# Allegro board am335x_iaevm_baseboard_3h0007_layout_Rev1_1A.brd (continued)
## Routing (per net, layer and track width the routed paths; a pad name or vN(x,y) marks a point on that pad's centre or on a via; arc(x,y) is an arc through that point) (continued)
VMMC: length 290.5
  TOP w0.508: v1(121.7,18.45) 120.69,18.45 112.94,26.2 106.46,26.2 104.94,24.68 104.94,23.85 104.05,22.96 99.16,22.96 97.19,20.99 v1(93.89,20.99) ; v1(125.89,53.5) 129.39,53.5 131.8,55.92 151.24,55.92 152.21,54.95 157.95,54.95 v1(158.91,55.92) ; R477.1 81.69,27.85 v1(80.68,27.85) ; v1(157.39,134.21) 157.33,134.28 130.97,134.28 130.78,134.47 v1(128.5,134.47) v1(123.48,134.47) ; v1(121.45,98.14) 120.37,97.07 v1(115.42,97.07)
  BOTTOM w0.508: v1(125.89,53.5) 125.64,53.5 124.88,52.74 124.88,33.12 J19.13 124.94,30.77 124.94,26.07 124.56,25.69 123.1,25.69 121.96,24.55 121.96,18.71 v1(121.7,18.45) ; v1(157.39,134.21) 157.39,98.34 159.03,96.69 159.03,56.95 158.91,56.83 v1(158.91,55.92) ; FB4.2 128.5,134.46 v1(128.5,134.47) ; v1(121.45,98.14) 119.65,99.95 119.65,114.31 121.39,116.05 121.39,118.91 120.56,119.73 120.56,129.2 123.48,132.12 v1(123.48,134.47) ; v1(80.68,27.85) 80.3,27.85 79.67,27.22 79.67,25.18 80.56,24.29 84.75,24.29 85.13,23.91 92.62,23.91 93.89,22.64 v1(93.89,20.99)
  BOTTOM w0.635: FB5.2 v1(115.42,97.07)
VPLL: length 129.3
  TOP w0.508: J19.15 122.66,27.98 v1(108.75,27.98) ; v1(55.84,54.39) 63.99,54.39 65.47,52.92 71.05,52.92 71.67,52.3 72.23,52.3 72.64,51.89 72.89,51.64 73.67,50.87 81.86,50.87 82.46,50.27 86.84,50.27 87.35,50.77 98.33,50.77 98.72,51.15 106.17,51.15 106.68,51.66 109.45,51.66 v1(109.51,51.73) ; R473.2 v1(109.51,37.88)
  BOTTOM w0.121: v1(109.51,51.73) 109.51,51.47
  BOTTOM w0.508: 109.51,51.47 v1(109.51,37.88) 109.51,35.66 108.75,34.9 v1(108.75,27.98) ; v1(55.84,54.39) 55.84,58.96 56.04,59.16 56.04,76.68 FB9.2
VPMIC_VRTC: length 6.4
  TOP w0.203: U4.29 90.05,37.9 90.26,38.11 90.64,38.11 90.74,38.21
  TOP w0.381: 90.74,38.21 v1(91.53,38.21)
  BOTTOM w0.508: v1(91.53,38.21) 91.6,38.29 C97.1 R53.1 93.51,38.39 R60.2
VPP: length 0.6
  TOP w0.381: v2(87.4,81) U2.M5
VPWRIN_FUSED: length 2.7
  TOP w0.502: 74.69,10.2 SW1.1 ; SW1.1 75.6,11.11 ; SW1.1 75.6,9.28
VPWRIN_JCK: length 8.7
  TOP w0.502: 55.79,12.97 J1.1 ; J1.1 53.61,15.15 ; J1.1 57.97,15.15 ; J1.1 55.79,17.33
VREFP_ADC: length 15.6
  TOP w0.102: U2.B9 78.73,84.6 78.33,85 77.1,85
  TOP w0.121: 77.1,85 76.98,84.88 75.62,84.88 74.61,85.89 74.08,85.89 73.52,86.45 72.07,86.45 71.78,86.16 71.78,86.16 71.77,86.15 70.02,86.15 C10.1 C9.1 68.13,86.24 68.01,86.24 67.35,86.91 67.35,89.19
VRTC: length 143.9
  TOP w0.254: U1.8 63.3,100.86 v1(63.28,100.88) 63.28,99.48 63.4,99.36 U1.5
  TOP w0.508: v1(64.05,51.09) 65.65,51.09 66.08,51.52 70.26,51.52 70.37,51.42 70.58,51.42 71.09,50.9 v1(71.28,50.9) ; v1(61.19,59.28) 62.14,58.33 v1(63.66,58.33)
  TOP w0.635: v1(120.05,41.31) 111.29,41.31 107.8,44.8 97.64,44.8 v1(94.14,41.31)
  BOTTOM w0.508: 92.75,40.17 C91.1 v1(94.14,41.31) ; C1.1 63.41,100.75 v1(63.28,100.88) 62.84,100.43 62.84,98.79 62.65,98.6 62.65,96.39 62.05,95.8 62.05,89.43 62.53,88.95 62.53,87.92 63.28,87.17 63.28,83.61 63.91,82.98 63.91,82.09 64.3,81.7 64.3,72.05 61.19,68.93 61.19,61.46 61.24,61.41 61.24,59.82 61.19,59.77 v1(61.19,59.28) ; v1(63.66,58.33) 63.66,56.74 64.31,56.1 64.31,52.81 64.05,52.55 v1(64.05,51.09) 63.47,50.52 61.22,50.52 R505.2 ; v1(71.28,50.9) 75.92,50.9 77.38,49.44 77.38,46.27 77.76,45.88 77.76,41.19 78.43,40.52 78.43,40.39 80.48,38.34 82.32,38.34 v1(83.1,37.57) 83.6,37.06 R54.2
  BOTTOM w0.635: J19.3 121.89,55.54 121.89,46.65 120.05,44.8 v1(120.05,41.31)
  vias: v1(86.14,25.31) v1(86.14,24.55)
VUSB_VBUS0: length 97.4
  TOP w0.508: v1(104.66,100.62) 97.36,100.62 R563.1
  TOP w0.762: v1(137.51,160.57) C262.1 v1(136.33,159.38)
  LY3 w0.508: v1(133.51,152.37) v1(105.47,152.37)
  LY4 w0.508: v1(104.66,100.62) 103.69,101.59 103.69,114.69 104.48,115.48 104.48,119.54 104.02,120 104.02,122.85 104.38,123.21 104.38,146.64 104.02,147 104.02,151.7 104.7,152.37 v1(105.47,152.37)
  BOTTOM w0.502: J36.1 136.44,154.94 ; J36.1 137.48,153.9 ; J36.1 135.39,153.9 ; J36.1 136.44,152.86
  vias: v1(132.02,164.76) v1(132.88,164.76) v1(133.77,164.73) v1(134.15,151.61) v1(134.72,152.37) v1(135.48,151.61) v1(136.05,152.37)
VUSB_VBUS1: length 114.8
  TOP w0.502: 150.95,157.71 J37.1 ; J37.1 151.99,156.67 ; J37.1 151.99,158.75 ; J18.1 149.45,166 ; J18.1 150.44,165.01 ; J18.1 149.45,164.02 ; J18.1 148.46,165.01
  TOP w0.508: v1(104.76,106.31) 103.92,105.47 93.7,105.47 93.38,105.15 R564.1
  TOP w0.635: v1(144.06,160.44) C265.1 v1(145.16,159.19)
  LY3 w0.508: v1(105.17,150.13) 105.17,150.18 106.73,151.74 130.25,151.74 131.46,150.53 140.88,150.53 v1(141.77,151.42)
  LY4 w0.508: v1(105.17,150.13) 105.17,148.68 105.7,148.14 105.7,109.31 104.76,108.37 v1(104.76,106.31)
  BOTTOM w0.502: 150.95,157.71 J37.1 ; J37.1 151.99,158.75 ; J37.1 153.03,157.71 ; J37.1 151.99,156.67 ; 149.45,164.02 J18.1 ; J18.1 150.44,165.01 ; J18.1 148.46,165.01 ; J18.1 149.45,166
  vias: v1(142.4,152.37) v1(143.1,151.42) v1(143.67,152.37) v1(144.37,151.42) v1(147.55,163.8) v1(148.31,163.87) v1(149.14,163.74)
N17759: length 6.1
  TOP w0.121: Y2.1 104.45,83.75 104.18,83.48 C5.1 100.95,83.48 R8.2 R7.1
N120395: length 1.7
  TOP w0.121: R50.1 84.09,18.18 D3.2
N124510: length 2.9
  TOP w0.121: v1(31.41,95.54) J2.4
  BOTTOM w0.121: R73.2 v1(31.41,95.54)
N150689: length 13.1
  TOP w0.121: R5.2 68.25,79.41 67.79,78.96 67.79,78.59 67.8,78.58 67.8,76.44 67.47,76.11 66.8,76.11 C3.2 62.86,76.02 61.76,77.13 61.76,78.78 Y1.1
N194366: length 15
  TOP w0.102: U2.A9 77.1,84.6
  TOP w0.121: 67.35,83.48 67.35,85.76 67.7,85.41 67.96,85.41 C9.2 C10.2 70.14,85.25 70.14,85.51 70.54,85.9 71.87,85.9 71.88,85.91 71.89,85.91 72.18,86.2 73.38,86.2 73.95,85.64 74.51,85.64 75.52,84.63 77.07,84.63 77.1,84.6
N17034041: length 2.7
  TOP w0.121: v1(153.96,69.13) SW3.1
  BOTTOM w0.121: R114.2 v1(153.96,69.13)
N17034069: length 2.7
  TOP w0.121: v1(153.96,66.59) SW3.2
  BOTTOM w0.121: R115.2 v1(153.96,66.59)
N17034107: length 2.7
  TOP w0.121: v1(153.96,64.05) SW3.3
  BOTTOM w0.121: R116.2 v1(153.96,64.05)
N17034117: length 2.7
  TOP w0.121: v1(153.96,61.51) SW3.4
  BOTTOM w0.121: R117.2 v1(153.96,61.51)
N17034161: length 2.7
  TOP w0.121: v1(153.96,58.97) SW3.5
  BOTTOM w0.121: R118.2 v1(153.96,58.97)
N17034171: length 2.7
  TOP w0.121: v1(153.96,56.43) SW3.6
  BOTTOM w0.121: R119.2 v1(153.96,56.43)
N17034215: length 2.7
  TOP w0.121: v1(153.96,53.89) SW3.7
  BOTTOM w0.121: R120.2 v1(153.96,53.89)
N17034225: length 2.7
  TOP w0.121: SW3.8 v1(153.96,51.35)
  BOTTOM w0.121: R121.2 v1(153.96,51.35)
N17107785: length 3.6
  TOP w0.203: U4.18 93.1,33.49 94.04,34.43 v1(94.04,35.01)
  BOTTOM w0.381: C98.1 94.4,34.66 v1(94.04,35.01)
N17298950: length 2.2
  TOP w0.121: U18.6 C179.1
N17298952: length 5
  TOP w0.121: C177.1 107.78,24.37 108.55,24.37 108.72,24.19 108.72,22.01 108.47,21.75 U18.2
N17298960: length 2.5
  TOP w0.121: U18.3 105.83,20.48 C176.2
N17298962: length 2.2
  TOP w0.121: 104.94,19.09 105.07,19.21 U18.4
N17298964: length 2.2
  TOP w0.121: U18.5 105.07,17.94 C178.2
N17298974: length 2.4
  TOP w0.121: U18.1 105.57,23.02 C176.1
N17345501: length 2.7
  TOP w0.121: v1(153.96,91.73) SW4.1
  BOTTOM w0.121: R122.2 v1(153.96,91.73)
N17345515: length 2.7
  TOP w0.121: v1(153.96,89.19) SW4.2
  BOTTOM w0.121: R123.2 v1(153.96,89.19)
N17345519: length 2.7
  TOP w0.121: v1(153.96,86.65) SW4.3
  BOTTOM w0.121: R124.2 v1(153.96,86.65)
N17345529: length 2.7
  TOP w0.121: v1(153.96,84.11) SW4.4
  BOTTOM w0.121: R125.2 v1(153.96,84.11)
N17345551: length 2.7
  TOP w0.121: v1(153.96,81.57) 155.61,81.57
  BOTTOM w0.121: R126.2 v1(153.96,81.57)
N17345553: length 2.7
  TOP w0.121: v1(153.96,79.03) SW4.6
  BOTTOM w0.121: R127.2 v1(153.96,79.03)
N17345567: length 2.7
  TOP w0.121: v1(153.96,76.49) SW4.7
  BOTTOM w0.121: R128.2 v1(153.96,76.49)
N17345577: length 2.7
  TOP w0.121: v1(153.96,73.95) SW4.8
  BOTTOM w0.121: R129.2 v1(153.96,73.95)
N17563948: length 121.5
  TOP w0.121: v1(40.5,116.32) 29.53,116.32 28.05,114.85 25.8,114.85 25.68,114.97 24.4,114.97 22.87,116.5 v1(22.86,116.5) ; Q1.G 10.44,88.54 R86.2 10.45,89.45 10.2,89.7 9.82,89.7 v1(9.31,90.21) ; 72.68,112.18 v1(73.62,112.18) ; R84.1 76.72,104.66 v1(76.72,104.94) ; R509.1 v1(89.95,112.51)
  LY3 w0.133: v1(73.62,112.18) 73.67,112.13 v1(76.49,112.13) 76.52,112.13 77.38,112.99 89.47,112.99 v1(89.95,112.51) ; v1(73.62,116.5) 73.42,116.7 41.49,116.7 41.11,116.32 v1(40.5,116.32)
  BOTTOM w0.121: v1(22.86,116.5) 22.86,115.39 22.14,114.67 22.14,112.08 21.2,111.15 21.2,104.38 16.55,99.73 12.61,99.73 9.57,96.7 9.57,92.62 9.31,92.35 v1(9.31,90.21) ; v1(73.62,116.5) v1(73.62,112.18) ; v1(76.49,112.13) 76.72,111.9 v1(76.72,104.94)
N17563994: length 1.9
  TOP w0.121: D4.2 5.48,88.43 v1(4.51,88.43)
  BOTTOM w0.121: R80.1 v1(4.51,88.43)
N17563997: length 2.7
  TOP w0.121: D4.1 7.66,86.16 Q1.D
N17564510: length 2.8
  TOP w0.121: D5.1 5.75,82.09 Q2.D
N17564514: length 2
  TOP w0.121: D5.2 v1(4.48,84.09)
  BOTTOM w0.121: R81.1 4.58,84.11 4.57,84.09 v1(4.48,84.09)
N17564644: length 2.8
  TOP w0.121: D6.1 5.75,77.65 Q3.D
N17564648: length 2
  TOP w0.121: v1(4.48,79.67) 5.48,79.67 D6.2
  BOTTOM w0.121: R82.1 v1(4.48,79.67)
N17564780: length 2.7
  TOP w0.121: Q4.D 5.62,73.2 D7.1
N17564784: length 2
  TOP w0.121: D7.2 v1(4.48,75.33)
  BOTTOM w0.121: R83.1 4.58,75.35 4.57,75.33 v1(4.48,75.33)
N17564892: length 199.4
  TOP w0.121: v1(9.44,85.13) 10.32,85.13 10.58,84.87 R93.2 10.57,84.1 Q2.G ; R87.1 77.25,101.81 v1(76.69,102.37) 77,102.68 77,104.56 R88.1 v1(78.55,106.11) ; v1(77.79,112.2) 85.08,112.2 R510.1 ; v1(22.64,156.69) v1(53.38,156.69)
  LY3 w0.133: v1(76.69,102.37) 76.48,102.59 73.26,102.59 72.93,102.91 68.28,102.91 67.8,103.39 53.28,103.39 52.36,104.3 43.19,104.3 40.97,102.08 23.72,102.08 23.46,101.82 23.09,101.82 22.18,102.73 v1(22.18,103.38)
  LY4 w0.133: v1(77.79,112.2) 78.55,111.44 v1(78.55,106.11)
  BOTTOM w0.121: v1(53.38,156.69) 58.14,156.69 v1(58.58,156.25) ; v1(22.64,156.69) 22.64,148.2 23.21,147.63 23.21,117.41 23.36,117.26 23.36,114.97 23.21,114.82 23.21,112.34 21.45,110.57 21.45,104.73 22.18,104 v1(22.18,103.38) 22.15,103.38 18.24,99.47 12.73,99.47 9.82,96.56 9.82,87.17 9.44,86.78 v1(9.44,85.13)
N17564904: length 244.4
  TOP w0.121: v1(24.04,156.12) v1(54.14,156.12) ; R89.1 R90.1 70.52,103.42 59.47,103.42 58.46,104.42 42.76,104.42 41.28,102.94 35.65,102.94 35.63,102.97 35.26,102.97 35.24,102.94 v1(23.66,102.94) ; Q3.G 9.12,79.67 R95.2 10.58,80.3 v1(10.07,80.81) ; R511.1 v1(87.79,112.51)
  LY3 w0.133: v1(87.79,112.51) 79.21,112.51 77.37,110.67 71,110.67 70.87,110.81 48.63,110.81 42.61,104.79 34.23,104.79 32.38,102.94 v1(23.66,102.94)
  BOTTOM w0.121: v1(10.07,80.81) 10.07,96.43 12.86,99.22 18.91,99.22 22.63,102.94 v1(23.66,102.94) 23.66,104.05 21.69,106.02 21.69,110.46 23.46,112.23 23.46,114.64 23.61,114.79 23.61,120 23.46,120.15 23.46,148.24 23.13,148.58 23.13,155.21 v1(24.04,156.12) ; v1(57.31,156.12) v1(54.14,156.12)
N17564916: length 152.7
  TOP w0.121: v1(46.52,136.56) 48.42,134.66 53.55,134.66 54.44,133.77 58.84,133.77 v1(59.6,133.01) ; v1(10.58,76.08) R94.2 10.57,75.21 Q4.G ; v1(23.28,102.27) 23.51,102.5 34.76,102.5 34.78,102.53 v1(35.44,102.53) 35.9,102.53 35.93,102.5 41.19,102.5 42.86,104.18 58.33,104.18 59.34,103.17 69.68,103.17 71.03,101.81 71.03,99.48 71.28,99.23 71.45,99.23 71.46,99.23 71.87,99.23 71.88,99.23 72.47,99.23 73.51,98.19 73.51,97.64 R91.1 ; v1(36.64,113.07) 39.05,113.07 41.59,115.61 R92.1 v1(46.9,117.28)
  BOTTOM w0.121: v1(46.52,136.56) 46.52,135.29 46.9,134.91 v1(46.9,117.28) ; v1(23.28,102.27) 22.31,102.27 19.01,98.97 13.04,98.97 10.32,96.25 10.32,81.7 10.58,81.44 v1(10.58,76.08) ; R512.1 v1(59.6,133.01) ; v1(36.64,113.07) 35.44,111.87 v1(35.44,102.53)
N17574941: length 2.1
  TOP w0.121: R1.1 59.46,100.86 U1.1
N17684279: length 4.4
  TOP w0.121: R239.1 v1(129.45,79.79)
  BOTTOM w0.102: J8.12 132.12,79.54 130.72,79.54
  BOTTOM w0.121: 130.72,79.54 129.7,79.54 v1(129.45,79.79)
N17684406: length 4.9
  TOP w0.121: U4.33 88.45,37.36 88.36,37.44 v1(88.36,37.53)
  BOTTOM w0.203: v1(88.36,37.53) 88.07,37.53 87.62,37.98 87.62,39.03 87.79,39.2 R63.1
N17710761: length 4.8
  TOP w0.102: v2(84.2,79.4) U2.J3
  BOTTOM w0.102: 84.2,77.4 v2(84.2,79.4)
  BOTTOM w0.121: 84.2,77.4 84.2,76.93 83.36,76.09 83.36,75.93 R22.2
N17828529: length 2.5
  TOP w0.102: U2.G2 83,79 83.35,78.65 v2(83.35,77.63)
  BOTTOM w0.102: 83.12,77.4 v2(83.35,77.63)
  BOTTOM w0.121: TP2.1 83.03,77.32 83.12,77.4
N18136628: length 2.7
  TOP w0.121: v1(139.74,72.05) 139.67,71.98 U7.7
  BOTTOM w0.121: v1(139.74,72.05) 139.74,70.9
N18365790: length 3
  TOP w0.203: U4.39 85.72,35.09 85.71,35.1 85.02,35.1 v1(84.78,35.34)
  BOTTOM w0.381: R57.1 84.65,35.47 v1(84.78,35.34)
N18368859: length 1.9
  TOP w0.203: R69.2 93.26,23.78 U6.7
N19440113: length 0.4
  TOP w0.121: U24.B2 U24.B1
N19440133: length 0.4
  TOP w0.121: U24.D2 U24.D1
N19440219: length 2.9
  TOP w0.121: U24.A3 U24.B3 U24.C4 U24.D4 155.59,144.71 C264.1
N19490589: length 9.9
  TOP w0.102: 77.1,80.08 77.2,80.08 77.21,80.07 77.93,80.07 U2.A3
  TOP w0.121: 77.1,80.08 76.39,80.08 75.74,79.42 71.89,79.42 71.51,79.03 71.16,79.03 70.78,78.66 69.9,78.66 TP24.1
N19558182: length 2.1
  TOP w0.121: R544.1 59.97,35.65 U32.2
N19577113: length 3.4
  TOP w0.121: U4.26 91.25,37.21 91.41,37.38 v1(92.49,37.38)
  BOTTOM w0.121: v1(92.49,37.38) 92.11,36.99 92.11,36.36 91.86,36.11
N19577116: length 4.7
  TOP w0.121: v1(93.38,34.45) 92.82,33.89 U4.19
  BOTTOM w0.121: R60.1 93,36.99 92.64,36.63 92.64,35.2 v1(93.38,34.45)
N21001557: length 9.1
  TOP w0.121: SW5.1 6.8,43.4 7.94,44.54 v1(7.94,45.25) 7.07,45.25 6.8,45.52 SW5.2
  BOTTOM w0.121: R112.2 R156.2 v1(7.94,45.25)
N21001559: length 8
  TOP w0.635: v1(10.83,43.34) 10.8,43.25 SW5.3 ; SW5.4 v1(10.8,45.45)
  BOTTOM w0.121: v1(10.83,43.34) 10.8,43.38 v1(10.8,45.45) 10.83,45.48 R559.1 R560.2
N21339295: length 1.8
  TOP w0.121: R23.2 129.39,161.73 128.6,160.95 Q5.D

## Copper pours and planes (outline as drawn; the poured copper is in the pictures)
DGND on TOP: 155.36,146.34 154.6,146.34 154.09,145.83 154.09,143.8 153.96,143.67 153.07,143.67 152.95,143.8 152.95,144.56 152.44,144.56 151.42,145.58 147.48,145.58 147.36,145.45 147.36,142.91 147.74,142.53 156.37,142.53 156.5,142.66 156.5,146.34 156.37,146.34 156.25,146.21 156.25,145.83 155.99,145.58 155.99,144.06 155.1,144.06 155.1,145.83 155.36,146.09
DGND on LY2_GND, LY5_GND: 1.27,1.27 168.73,1.27 168.73,168.73 1.27,168.73
V1_8D on LY4: 134.78,125.64 137.96,125.64 137.96,116.62 134.28,116.62 134.28,50.08 132.24,50.08 132.24,88.3 129.83,88.3 129.83,122.34 134.53,122.34 134.53,125.39
V3_3D on TOP: 113.96,24.93 112.05,24.93 111.92,24.8 111.92,23.91 111.67,23.66 110.65,23.66 110.65,22.64 110.78,22.52 113.83,22.52 113.96,22.64
V3_3D on BOTTOM: 111.42,22.01 113.58,22.01 113.96,22.39 113.96,24.68 113.7,24.93 111.29,24.93 111.16,24.8 111.16,22.26
V3_3D on LY4: 47.28,139.1 47.28,139.23 36.87,139.23 36.87,115.1 10.07,115.1 10.07,95.16 28.36,95.16 28.36,61.25 23.66,61.25 23.66,51.35 12.1,51.35 12.1,47.79 1.43,47.79 1.43,1.31 131.48,1.31 131.48,25.82 102.27,25.82 102.27,7.66 51.22,7.66 51.22,72.33 32.93,72.33 32.93,99.35 13.63,99.35 13.63,104.3 68.24,104.3 68.24,120.31 75.6,120.31 75.6,146.85 64.43,146.85 64.43,139.1
V5_0D on TOP: 155.1,147.87 155.36,147.61 155.36,146.98 153.33,146.98 152.82,146.47 152.82,144.94 152.69,144.82 152.44,144.82 151.42,145.83 147.36,145.83 146.85,146.34 146.85,147.99 147.48,148.63 152.06,148.63 152.82,147.87
V5_0D on LY4: 152.95,148.63 152.95,70.14 134.66,70.14 134.66,116.37 138.21,116.37 138.21,125.89 134.53,125.89 134.15,125.51 134.15,122.97 129.83,122.97 129.83,148.63
VBAT on TOP: 83.35,10.58 93.38,10.58 93.89,11.09 93.89,14.01 91.48,16.42 91.48,18.71 91.22,18.96 91.22,21.88 87.79,21.88 87.54,21.63 86.65,21.63 86.65,21.75 86.52,21.75 86.52,22.26 82.97,22.26 82.97,18.96 86.14,18.96 86.27,18.83 86.27,14.9 85.89,14.52 78.4,14.52 78.33,14.45 77.82,14.45 77,13.63 77,8.8 77.25,8.55 78.9,8.55 79.67,9.31 79.67,11.21 80.05,11.59 82.33,11.59
VBAT on TOP: 10.96,99.86 14.77,99.86 14.9,99.99 14.9,100.62 14.64,100.88 10.96,100.88
VBAT on TOP: 159.8,146.47 159.8,149.39 159.55,149.64 158.15,149.64 157.39,148.88 157.39,148.25 156.63,147.48 156.63,146.85 157.14,146.85 157.52,146.47
VBAT on LY4: 106.21,163.74 106.21,157.9 120.43,157.9 120.43,42.46 98.34,42.46 98.34,37.88 83.86,37.88 83.86,22.9 56.68,22.9 56.68,84.11 50.71,84.11 50.71,103.8 14.01,103.8 14.01,99.61 33.44,99.61 33.44,72.63 51.6,72.63 51.6,8.04 101.89,8.04 101.89,26.33 131.86,26.33 131.86,87.29 128.82,87.29 128.82,148.88 153.33,148.88 153.33,147.99 159.3,147.99 159.3,154.47 134.53,154.47 134.53,163.74
VBUS1_OTG_CAP on TOP: 153.38,161.15 153.38,156.91 154.09,156.2 159.6,156.2 159.9,156.5 159.9,160.13 158.66,161.38 153.61,161.38
VDD1_SMPS on TOP: 72.3,37.68 74.99,37.68 75.25,37.43 75.25,36.21 75.02,35.98 72.45,35.98 72.27,36.16 72.27,37.65
VDD1_SMPS on TOP: 80.43,43.34 81.7,43.34 82.21,43.85 82.21,46.33 80.05,46.33 80.05,43.73
VDD1_SMPS on LY3: 125.2,51.22 125.2,45.5 121.7,45.5 121.7,44.11 76.11,44.11 76.11,34.07 66.71,34.07 66.71,47.28 117.39,47.28 117.39,51.22
VDD2_SMPS on TOP: 76.24,36.49 77.76,36.49 78.27,36.99 78.27,38.65 78.14,38.77 76.24,38.77 76.11,38.65 76.11,36.61
VDD2_SMPS on TOP: 68.74,49.06 69.51,49.06 69.89,48.68 70.52,48.68 70.78,48.42 70.78,47.28 70.27,46.77 69.89,46.77 69.76,46.9 69.76,47.79 69.63,47.92 68.74,47.92
VDD2_SMPS on LY4: 78.14,39.03 75.98,39.03 75.98,32.63 72.43,32.63 72.43,48.93 69.25,48.93 69.25,29.48 78.14,29.48
VDD3_SMPS on TOP: 90.97,44.74 93.13,44.74 93.26,44.87 93.26,46.52 92.87,46.9 91.1,46.9 90.84,46.65 90.84,44.87
VDD3_SMPS on BOTTOM: 92.62,49.69 92.62,45 92.24,44.61 90.33,44.61 89.95,45 89.95,49.69 89.98,49.73 89.98,49.69
VDD_CORE on TOP: 72.55,46.77 72.55,45.76 72.81,45.5 75.09,45.5 75.6,46.01 75.6,46.9 75.22,47.28 73.06,47.28
VDD_CORE on BOTTOM: 73.06,47.28 72.55,46.77 72.55,45.76 72.81,45.5 75.09,45.5 75.6,46.01 75.6,46.77 75.09,47.28
VDD_CORE on LY3: 85.38,83.86 86.91,83.86 87.03,83.73 87.03,75.86 86.02,74.84 77.63,74.84 77.63,70.01 77.38,69.76 64.55,69.76 64.17,70.14 64.17,77.89 64.81,78.52 75.22,78.52 77.38,80.68 82.21,80.68
VDD_CORE on LY4: 82.33,86.97 82.33,81.57 86.02,81.57 86.02,82.33 86.78,82.33 86.78,83.98 88.56,83.98 88.56,88.49 88.37,88.68 85.32,88.68 84.43,87.79 83.92,87.79 83.1,86.97
VDD_MPU on TOP: 72.25,34.96 74.56,34.96 74.92,34.61 74.92,32.98 74.61,32.68 73.87,32.68 73.29,33.26 72.3,33.26 72.17,33.39 72.17,34.89
VDD_MPU on LY3: 84.37,88.43 84.62,88.18 84.62,87.79 84.24,87.41 84.24,85.25 83.73,84.75 82.33,84.75 81.83,84.24 81.83,83.86 81.19,83.22 80.3,83.22 80.17,83.1 78.14,83.1 75.86,80.81 67.22,80.81 66.97,80.56 64.55,80.56 64.43,80.68 64.43,82.71 73.06,82.71 74.21,83.86 76.11,83.86 79.03,86.78 79.54,86.78 79.92,86.4 80.43,86.4 80.94,85.89 81.44,86.4 81.44,88.43
VDDS_DDR on LY3: 67.09,69.51 67.09,54.52 67.35,54.27 103.67,54.27 105.19,55.79 105.19,65.7 106.46,66.97 106.46,69.68 106.01,70.14 104,70.14 103.36,69.51 91.5,69.51 90.49,68.49 90.49,66.41 89.57,65.49 89.06,65.49 89.06,66.66 87.79,67.93 87.79,69.51 85.05,69.51 86.93,67.63 86.93,65.82 86.91,65.8 86.35,65.8 86.32,65.82 86.32,66.89 83.7,69.51
VDDS_RTC on LY4: 80.43,82.9 80.43,80.62 69.82,80.62 69.82,81.83 71.6,83.6 79.73,83.6
VDDSHV2 on LY3: 19.87,113.04 19.87,110.65 22.59,107.94 42.07,107.94 47.64,113.5 76.44,113.5 76.85,113.91 79.49,113.91 80.71,115.12 80.71,117.94 80.12,118.53 77.15,118.53 76.72,118.1 76.72,116.89 75.98,116.15 73.23,116.15 73.14,116.06 43.93,116.06 43.6,116.39 42.02,116.39 38.11,112.48 23.25,112.48 22.52,113.22 20.05,113.22
VDDSHV4 on LY4: 42.2,143.42 42.2,164.88 61.51,164.88 61.51,163.61 105.96,163.61 105.96,157.64 117,157.64 117,148.75 114.34,148.75 114.34,155.49 76.62,155.49 76.62,147.23 57.7,147.23 57.7,143.42
VDDSHV6 on LY4: 141.26,1.27 141.26,1.43 132.24,1.43 132.24,49.57 134.66,49.57 134.66,69.89 153.45,69.89 153.45,147.61 159.68,147.61 159.68,154.85 134.91,154.85 134.91,163.87 61.76,163.87 61.76,165.26 41.82,165.26 41.82,143.42 58.33,143.42 58.33,146.98 63.92,146.98 63.92,139.74 36.49,139.74 36.49,115.35 9.82,115.35 9.82,94.65 28.1,94.65 28.1,61.51 23.41,61.51 23.41,51.73 11.72,51.73 11.72,48.17 1.31,48.17 1.31,168.69 143.42,168.69 143.42,168.73 168.28,168.73 168.73,168.28 168.73,1.72 168.28,1.27
AM335X_VDDS on LY3: 80.56,81.95 80.56,80.91 82.18,80.91 85.38,84.11 87.29,84.11 87.29,81.63 87.41,81.51 88.62,81.51 88.68,81.57 88.68,83.79 89.38,83.79 89.38,85.13 88.81,85.13 88.56,85.38 88.56,88.43 88.68,88.56 89.57,88.56 89.83,88.3 91.48,88.3 92.49,89.32 94.14,89.32 94.14,90.46 94.02,90.59 91.99,90.59 91.86,90.52 90.84,89.51 85.7,89.51 85.57,89.64 85.57,94.14 85.59,94.16 85.59,95.09 87.39,96.89 87.39,97.4 87.77,97.78 88.23,97.78 88.65,98.2 88.65,98.75 87.92,99.48 84.03,99.48 83.1,98.54 83.1,93 81.95,93 80.68,91.73 80.68,88.94 81.06,88.56 84.37,88.56 84.75,88.18 84.75,87.67 84.37,87.29 84.37,85.13 83.86,84.62 82.46,84.62 81.95,84.11 81.95,83.6 81.83,83.48 81.83,83.35 81.44,82.97 81.44,82.33 81.25,82.14 80.75,82.14
AM335X_VDDS_DDR on BOTTOM: 81.32,80.81 83.73,80.81 83.98,80.56 86.78,80.56 86.91,80.68 86.91,81.19 86.78,81.32 83.98,81.32 83.86,81.44 83.86,81.83 83.6,82.08 81.32,82.08 81.19,81.95 81.19,80.94
AM335X_VDDS_DDR on LY4: 82.33,81.32 82.33,80.56 87.79,80.56 87.79,81.44 88.56,81.44 88.56,81.98 88.81,82.23 89.29,82.23 89.83,81.7 92.62,81.7 92.62,82.87 92.42,83.07 92.01,83.07 91.88,83.2 91.88,83.25 91.27,83.86 86.91,83.86 86.91,82.21 86.14,82.21 86.14,81.32
AM335X_VDDSHV3 on LY3: 89.45,88.43 88.75,88.43 88.62,88.3 88.62,86.52 88.87,86.27 91.73,86.27 92.37,86.91 92.87,86.91 93.51,87.54 94.14,87.54 94.27,87.67 94.27,88.94 94.14,89.06 92.49,89.06 91.48,88.05 89.83,88.05
AM335X_VDDSHV6 on LY3: 48.93,83.98 66.84,83.98 67.86,82.97 72.94,82.97 74.14,84.17 76.05,84.17 79.03,87.16 79.54,87.16 80.05,86.65 80.43,86.65 80.81,86.27 81.06,86.27 81.32,86.52 81.32,88.43 80.94,88.43 80.17,89.19 80.17,91.48 79.49,92.16 76.77,92.16 75.67,91.06 75.67,88.24 73.57,86.14 48.81,86.14 48.81,84.11
AM335X_VDDSHV6 on LY4: 88.81,82.08 89.22,82.08 89.45,81.85 89.45,81.7 89.57,81.57 92.62,81.57 92.62,79.79 93.38,79.79 93.38,79.03 91.1,79.03 91.1,77.76 91.13,77.73 91.1,77.7 91.1,76.81 80.56,76.81 80.56,89.19 83.1,89.19 83.1,87.16 82.21,87.16 82.21,80.3 87.92,80.3 87.92,81.06 88.18,81.32 88.56,81.32 88.68,81.44 88.68,81.95
LDO_VRTC on TOP: 82.59,25.95 83.86,25.95 83.86,23.02 83.73,22.9 82.71,22.9 82.59,22.77 81.83,22.77 81.83,24.29 82.59,25.06
PWR_SMPS3 on TOP: 89.06,38.44 89.06,36.74 89.45,36.74 89.45,38.21 89.88,38.65 89.88,39 89.62,39.25 89.39,39.25 89.22,39.08 89.22,38.59
PWR_SWIO on TOP: 94.91,29.88 96.43,29.88 96.56,30.01 96.56,35.09 95.29,35.09 94.02,33.82 94.02,32.17 93.76,31.91 93.51,31.91 93.51,31.66 94.02,31.66 94.14,31.53 94.14,30.64
PWR_VAUX33 on LY4: 87.03,28.87 87.03,27.98 87.41,27.6 94.14,27.6 94.65,28.1 94.65,28.87 94.27,29.25 90.33,29.25 89.95,28.87
PWR_VDAC on TOP: 97.7,36.74 97.7,35.22 94.02,35.22 93.64,34.84 91.99,34.84 91.99,35.34 93,35.34 94.14,36.49 94.91,36.49 95.16,36.74
PWR_VDD1_SMPS on TOP: 80.17,41.31 81.95,41.31 82.46,41.82 87.41,41.82 88.05,41.19 88.18,41.19 88.56,40.8 89.32,40.8 89.32,45.38 88.81,45.88 83.1,45.88 82.46,45.25 82.46,43.6 81.83,42.96 80.43,42.96 80.05,42.58 80.05,41.44
PWR_VDD2_SMPS on TOP: 84.11,32.8 84.11,33.06 84.49,33.44 85.64,33.44 85.89,33.18 86.4,33.18 86.4,32.93 85.76,32.93 85.64,33.06 85.25,33.06 85,32.8
PWR_VDD2_SMPS on TOP: 76.49,35.98 77.76,35.98 79.03,37.25 80.81,37.25 80.94,37.12 80.94,31.91 80.56,31.53 79.54,31.53 77.89,33.18 76.75,33.18 76.49,33.44
PWR_VDD3_SMPS on TOP: 89.57,36.74 89.57,38.14 90.21,38.77 90.21,38.9 90.52,39.22 91.35,39.22 91.35,44.23 91.48,44.36 93.13,44.36 93.26,44.23 93.26,39.03 93,38.77 90.84,38.77 90.46,38.39 90.21,38.39 89.83,38.01 89.83,36.74
PWR_VDDIO on TOP: 93,30.39 93,30.64 92.62,31.03 91.6,31.03 91.6,30.26 92.24,30.26 92.49,30.01 92.62,30.01
PWR_VDIG2 on TOP: 87.92,27.47 87.92,28.36 88.3,28.74 88.3,29.63 88.68,30.01 88.94,30.01 88.94,27.47
PWR_VIO_SMPS on TOP: 97.57,35.09 97.57,29.88 97.83,29.63 99.48,29.63 99.73,29.37 99.73,27.98 99.86,27.85 102.65,27.85 102.91,28.1 102.91,30.14 100.24,32.8 100.24,34.96 100.11,35.09
PWR_VIO_SMPS on BOTTOM: 93.13,32.8 96.18,32.8 96.56,32.42 100.88,32.42 101.26,32.04 101.26,30.9 100.75,30.39 95.54,30.39 94.02,31.91 93.13,31.91
PWR_VMMC on TOP: 86.02,28.1 86.27,28.1 86.52,28.36 86.52,29.5 87.41,30.39 87.41,30.96 87.48,31.03 87.79,31.03 87.79,29.88 87.67,29.76 87.41,29.76 87.29,29.63 87.29,27.47 87.16,27.34 86.02,27.34
PWR_VPLL on TOP: 93.26,36.87 92.49,36.87 92.24,36.61 92.24,35.85 92.75,35.85 92.75,36.36 93,36.61 93.26,36.61
USB5V_FB on TOP: 155.36,146.85 153.45,146.85 153.07,146.47 153.07,144.06 153.33,143.8 153.83,143.8 153.96,143.93 153.96,145.83 154.6,146.47 155.36,146.47
VBCKUPBAT on TOP: 92.75,38.39 92.24,38.39 91.73,37.88 91.1,37.88 90.72,37.5 90.72,36.61 90.97,36.61 90.97,37.25 91.35,37.63 92.37,37.63 92.75,38.01
VPWRIN_FUSED on TOP: 65.95,8.8 75.73,8.8 76.49,9.56 76.49,13.88 74.59,15.79 74.59,22.39 64.05,22.39 63.54,21.88 63.54,11.21
VPWRIN_JCK on TOP: 51.6,12.36 56.81,12.36 58.97,14.52 58.97,20.99 58.2,21.75 51.98,21.75 50.96,20.74 50.96,13.5 51.6,12.86
VPWRIN_PREFUSE on TOP: 52.11,23.41 69.25,23.41 70.01,24.17 70.01,28.49 69.38,29.12 52.36,29.12 51.47,28.23 51.47,24.04
VRTC on TOP: 92.49,24.17 90.08,24.17 89.57,23.66 85.51,23.66 85.51,24.42 84.62,24.42 84.62,25.82 84.75,25.95 85.89,25.95 86.78,25.06 91.99,25.06 92.49,24.55
VRTC on LY3: 82.71,23.41 97.83,23.41 97.83,42.46 82.71,42.46 82.71,31.15 91.48,31.15 91.48,25.82 82.71,25.82
VUSB_VBUS0 on TOP: 131.74,166.51 131.74,164.98 131.61,164.86 131.61,162.44 132.12,162.44 132.12,163.46 132.88,164.22 134.15,164.22 134.15,165.11 132.63,165.11 132.37,165.37 132.37,166.51
VUSB_VBUS0 on TOP: 132.75,148.82 136.69,148.82 136.69,152.63 135.67,153.64 132.5,153.64 132.5,149.07
VUSB_VBUS0 on BOTTOM: 135.17,167.8 127.04,167.8 126.66,167.42 126.66,164.25 127.29,163.61 130.34,163.61 130.47,163.49 130.47,161.71 131.48,160.69 132.82,160.69 132.82,151.61 133.32,151.1 137.01,151.1 138.15,152.25 138.15,164.82
VUSB_VBUS1 on TOP: 140.82,148.37 145.07,148.37 145.07,152.82 144.94,152.95 141.01,152.95 140.75,152.69 140.75,148.44
VUSB_VBUS1 on TOP: 147.17,162.53 147.17,161.58 147.67,161.58 147.67,162.6 148.44,163.36 149.95,163.36 150.48,162.83 150.48,156.73 150.99,156.22 153,156.22 153,164.3 151.01,166.28 148.12,166.28 147.99,166.15 147.99,164.25 147.87,164.12 147.23,164.12 146.98,163.87 146.98,162.72
VUSB_VBUS1 on BOTTOM: 141.01,148.44 145.07,148.44 145.07,151.68 149.01,155.61 153.07,155.61 153.64,156.18 153.64,165.07 151.04,167.68 141.71,167.68 140.88,166.85 140.88,148.56
N19440113 on TOP: 160.31,153.07 156.5,153.07 156.5,148.12 156.12,147.74 156.12,146.98 156.25,146.85 156.37,146.85 156.5,146.98 156.5,147.48 157.26,148.25 157.26,149.01 158.28,150.02 160.31,150.02
N19440133 on TOP: 155.23,152.95 151.17,152.95 151.17,149.9 153.07,147.99 155.1,147.99 155.49,147.61 155.49,146.98 155.74,146.98 155.74,147.87 155.23,148.37

Small or netless copper shapes (teardrops, artwork), in the pictures only: 4 on TOP

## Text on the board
BOTTOM: LAYER 6 - SECONDARY SIDE | 6 | PN 3H0007
User.Comments: sdf | Green indicates power/gnd routing
TOP: LAYER 1 - PRIMARY SIDE | 1
Ref Des/Silkscreen Top: E4 | A4 | VBAT | 1 | GND | RESET | INT | VDDS_SRAM_CORE | VDDS_SRAM_MPU_BB | VDDA_ADC | VDDSHV6 | 5VDC | VDDS_RTC | VDDS_PLL_DDR | VDD CORE | ON | POWER | OFF | VDDSHV5V | VDDS | VDDA3P3V_USB0 | 3.0V 800uA | RS-232 0 | VDDSHV2 | VDDA1P8V_USB0 | USB0 | VDDSHV3 | USB1 | SD/MMC0 Card | VDDS_PLL_MPU | VDDS_DDR | VDDS_PLL_CORE_LCD | VDDS_OSC | VDDSHV1 | VDDSHV4 | SYSBOOT 0-7 | SYSBOOT 8-15 | ARM MPU | AM335x INDUSTRIAL EVM 15x15 Base Board | REV 1.1A | SN#:_________________ | ASSY PN 4P0018
LY2_GND: LAYER 2 - GND PLANE | 2
LY3: 3
LY4: 4
LY5_GND: LAYER 5 - PLANE | 5
DIMENSION: (OZ) | DRILL DRAWING | 13 | 9. PLATED THROUGH SLOT INDICATED WITH MULTIPLE DRILL HITS SHOULD BE | 11. DESIGN HAS INTENTIONAL SHORTS AT SENSE RESISTORS AS SHOWN IN IPC356 NETLIST. | 10. ALL VIAS TO HAVE SOLDERMASK. | FAB NOTES: | 1. ALL DIMENSIONS ARE IN INCHES, UNLESS | OTHERWISE NOTED. | 2. THE PWB SHALL BE FABRICATED TO IPC-6012, | CLASS 2 AND WORKMANSHIP SHALL CONFORM TO | IPC-A-600, CLASS 2. CURRENT REVISIONS. | 3. BOARD MATERIAL SHALL BE 180 Tg/350 Td ISOLA FR-370HR | OR EQUIVALENT, RoHS COMPLIANT AND LEAD FREE | ASSEMBLY CAPABLE.  BOARD MATERIAL SHALL | MEET OR EXCEED IPC-4101B. COLOR: NATURAL. | 4. BOARD MATERIAL & CONSTRUCTION TO BE U.L. | APPROVED AND MARKED ON THE FINISHED BOARD. | 5. MINIMUM COPPER WALL THICKNESS OF PLATED-THRU | HOLES TO BE .001 INCH, WITH A MINIMUM | ANNULAR RING OF .002 INCH. | 6. OVERALL BOARD THICKNESS TO BE .062 +/- 10% | AND APPLIES AFTER ALL LAMINATION AND PLATING | PROCESSES, MEASURED FROM COPPER TO COPPER. | 7. MAX. WARP & TWIST TO BE .0075 INCHES PER INCH. | 8. BOARD MUST BE ELECTRICALLY TESTED USING | SUPPLIED IPC-D-356 NETLIST. | FINISHED AS SMOOTH WALL BY VEDOR. | PROCESS NOTES: | 2. APPLY LPI SOLDERMASK OVER BARE COPPER (SMOBC), | COLOR: GREEN. SOLDERMASK SHALL | CONFORM TO IPC-SM-840, CLASS H. CURRENT REV. | 3. SOLDERMASK ARTWORK HAS ZERO (0) OVERSIZED PADS. | FABRICATION VENDOR IS ALLOWED TO ADJUST THE COMPONENT | SOLDERMASK PADS TO MEET THEIR TOOLING REQUIREMENTS. | 4. APPLY LPI SILKSCREEN OR EQUIVALENT PER THE ARTWORK. | COLOR: WHITE. | 1. PLATE ALL EXPOSED AREAS WITH ELECTROLESS | IMMERSION GOLD, NICKEL 150 MICROINCHES THK MIN | GOLD 5-15 MICROINCHES THK MIN. | LAYER 1 - PRIMARY SIDE - SIGNAL | LAYER 2 - GROUND PLANE | LAYER 3 - SIGNAL | LAYER 4 - SIGNAL | LAYER 5 - SPLIT POWER PLANE | LAYER 6 - SECONDARY SIDE - SIGNAL | LAYER# | COPPER WEIGHT | HALF+PLATING | 1 | IMPEDANCE CONTROL | +/- 10% | 50ohm SINGLE ENDED | TRACE WIDTH | 5.25 | 4.75 | TRACE WIDTH / SPACE | 90ohm DIFFERENTIAL | 4.5/6.5 | 5.0/7.0 | 100ohm DIFFERENTIAL | 3.75/7.25 | 4.00/8.00 | LAYER STACK-UP - ALL DIMENSIONS IN INCHES
720-2152-002: J6 | J4 | J3 | J1
User.5: 3H0007 | TEXAS INSTRUMENTS | 1.1A | 11-28-11 | TI-6005-01 | 12 | AM335x 15x15 IND BASEBOARD
User.9: FIGURE | SIZE | 8.0 | 10.0 | 18.0 | 26.0 | 36.0 | 40.0 | 43.0 | 63.0 | 91.0 | 120.0 | 140.0 | 33.0 | 70.0 | 110.0 | 250.0 | DRILL CHART: TOP to BOTTOM | ALL UNITS ARE IN MILS | TOLERANCE | +3.0/-3.0 | PLATED | NON-PLATED | QTY | 183 | 2141 | 9 | 60 | 4 | 194 | 6 | 1 | 2
